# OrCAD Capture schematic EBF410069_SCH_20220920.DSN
size A4; title: 野火_瑞萨启明6M5开发板原理图; rev: V0.1; note: RA6M5 MCU - Power; note: https://yehuosm.tmall.com
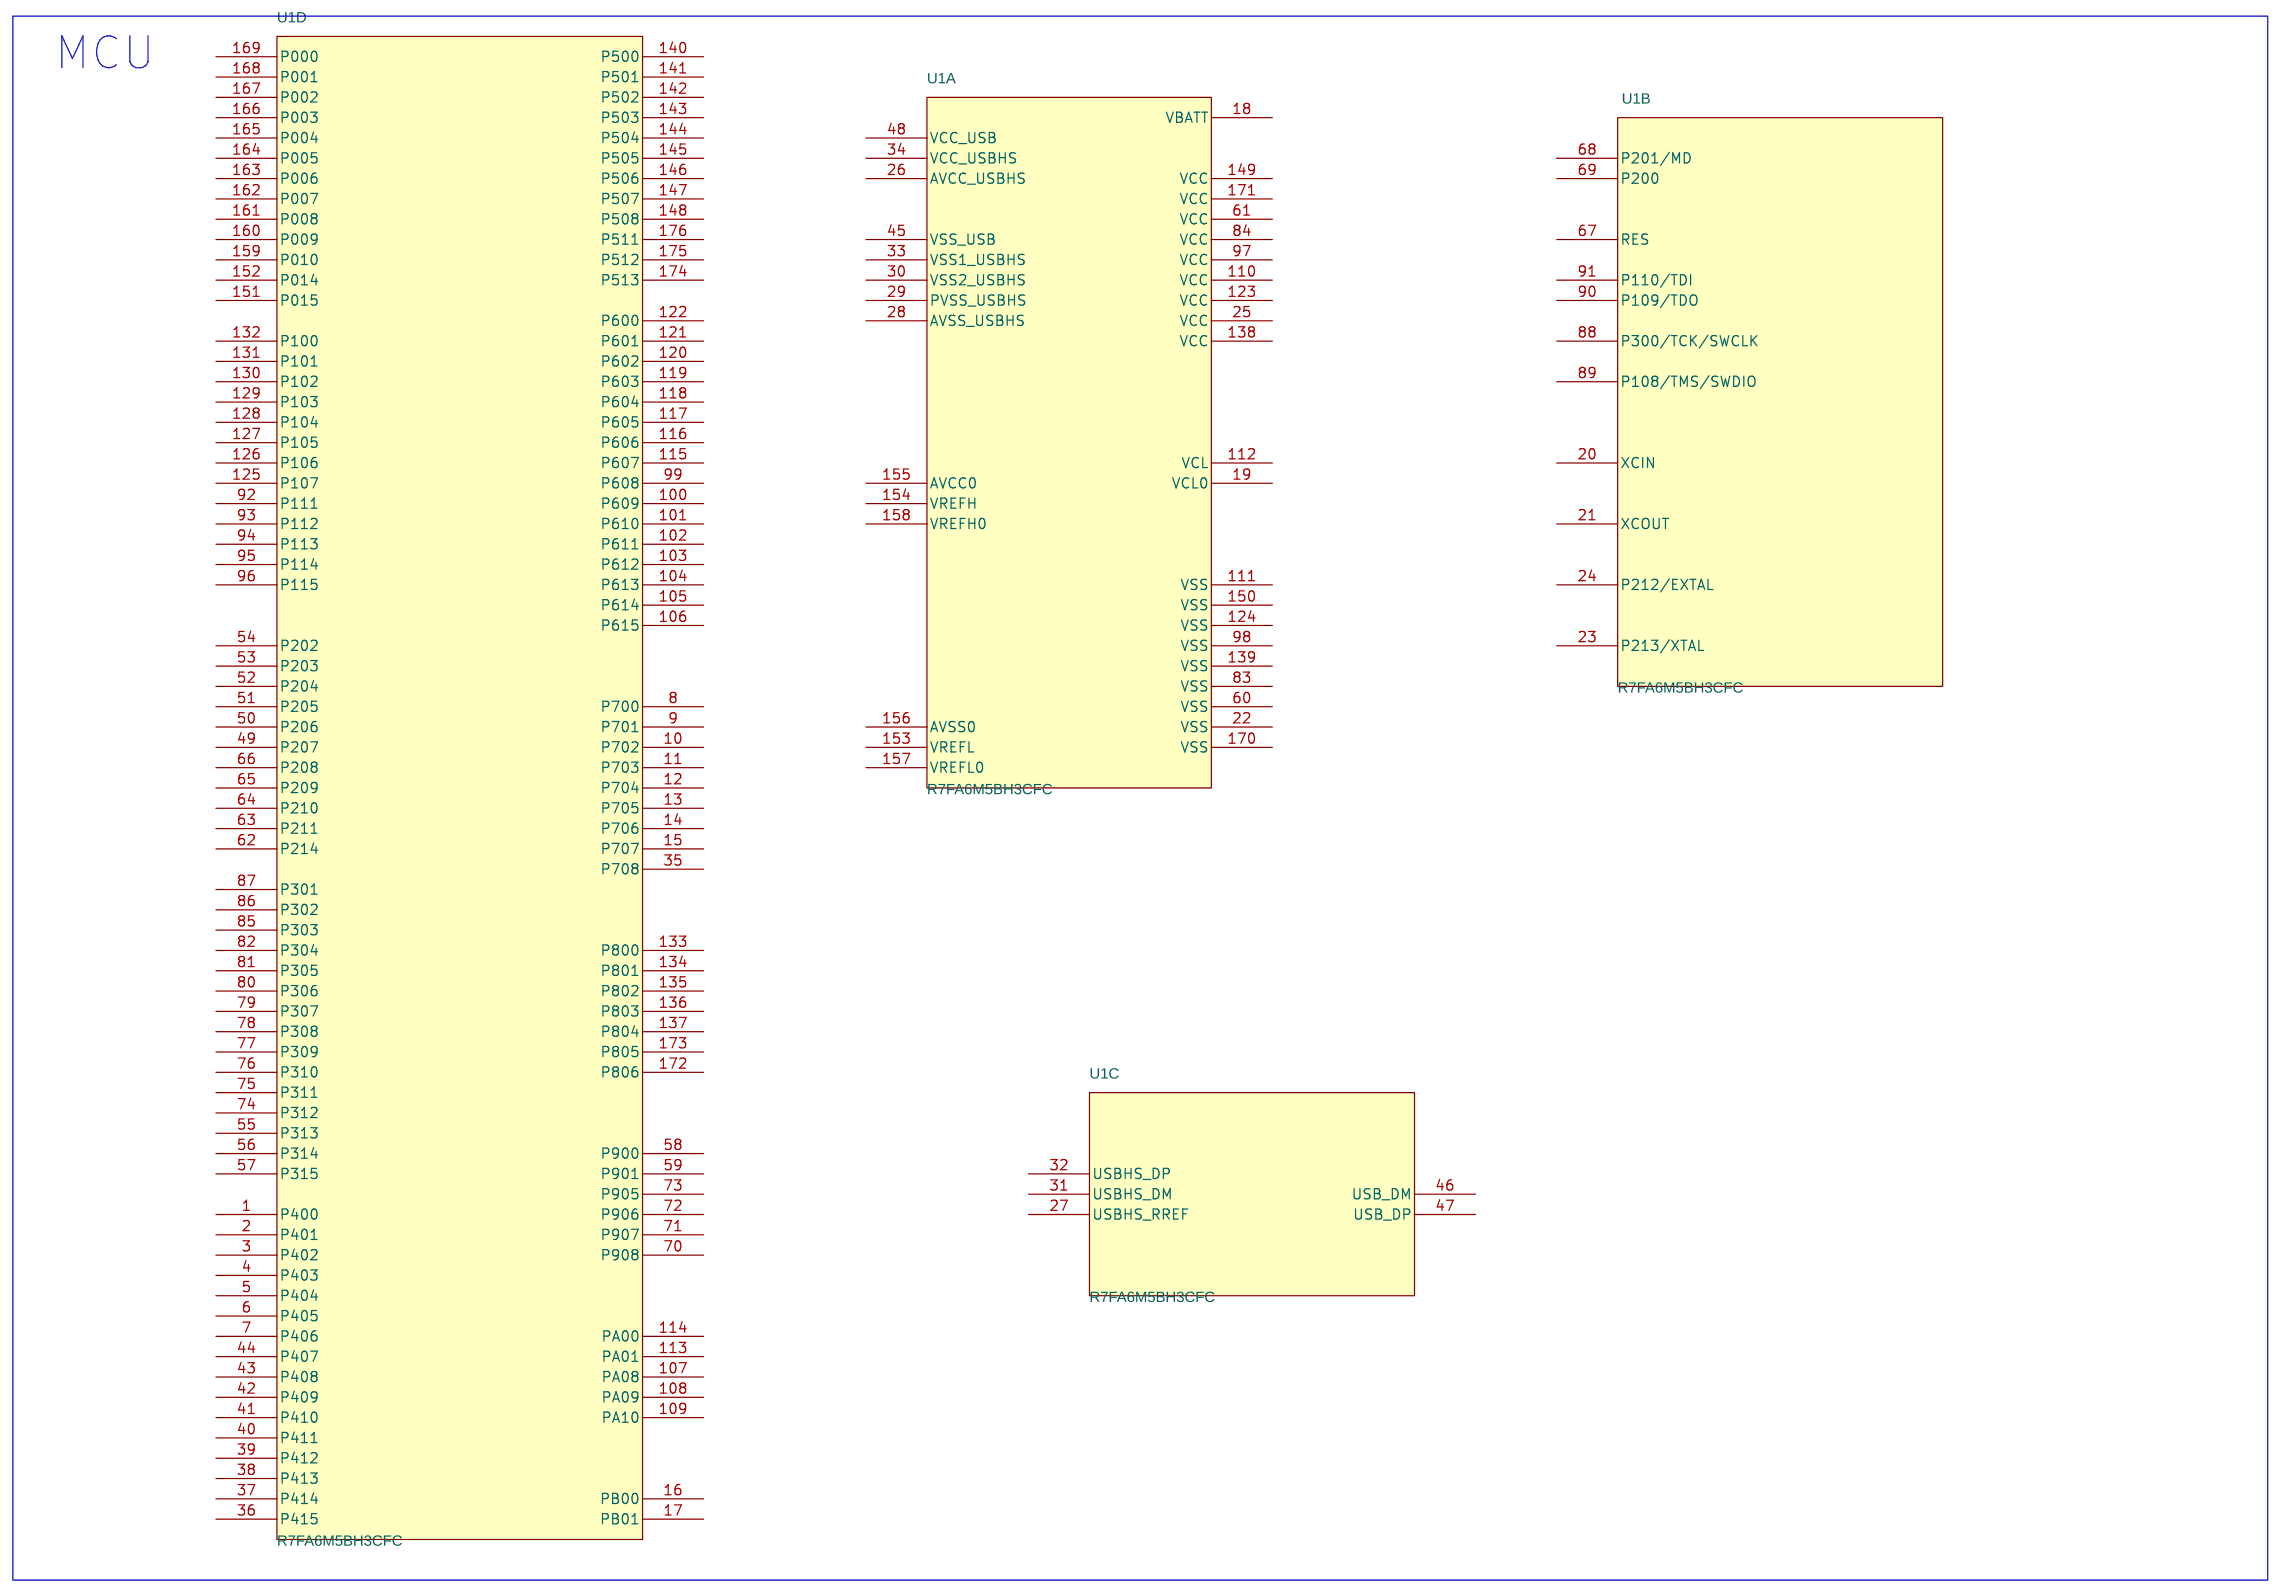
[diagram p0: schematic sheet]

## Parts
U1  R7FA6M5BH3CFC  [P-LFQFP176-24x24-0r50]  (sections A,B,C,D)

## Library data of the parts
U1 = R7FA6M5BH3CFC: 规格: 工作电压 2.7V~3.6V ROM 2M RAM 512K 主频 200MHz; 规格书: 瑞萨RA6M5系列引脚定义_电气特性与封装特性.pdf; 类别: 微控制器-ARM; 品牌: 瑞萨; 生命周期: 量产; 条码: EBF29120558

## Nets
AVCC_USBHS: U1.26(AVCC_USBHS)
AVSS_USBHS: U1.28(AVSS_USBHS)
PVSS_USBHS: U1.29(PVSS_USBHS)
VCC: U1.25(VCC) U1.61(VCC) U1.84(VCC) U1.97(VCC) U1.110(VCC) U1.123(VCC) U1.138(VCC) U1.149(VCC) U1.171(VCC)
VCC_USB: U1.48(VCC_USB)
VCC_USBHS: U1.34(VCC_USBHS)
VSS: U1.22(VSS) U1.60(VSS) U1.83(VSS) U1.98(VSS) U1.111(VSS) U1.124(VSS) U1.139(VSS) U1.150(VSS) U1.170(VSS)
VSS1_USBHS: U1.33(VSS1_USBHS)
VSS2_USBHS: U1.30(VSS2_USBHS)
VSS_USB: U1.45(VSS_USB)

Not connected (* = marked no-connect by the designer): U1 1(P400) 2(P401) 3(P402) 4(P403) 5(P404) 6(P405) 7(P406) 8(P700) 9(P701) 10(P702) 11(P703) 12(P704) 13(P705) 14(P706) 15(P707) 16(PB00) 17(PB01) 18(VBATT) 19(VCL0) 20(XCIN) 21(XCOUT) 23(P213/XTAL) 24(P212/EXTAL) 27(USBHS_RREF) 31(USBHS_DM) 32(USBHS_DP) 35(P708) 36(P415) 37(P414) 38(P413) 39(P412) 40(P411) 41(P410) 42(P409) 43(P408) 44(P407) 46(USB_DM) 47(USB_DP) 49(P207) 50(P206) 51(P205) 52(P204) 53(P203) 54(P202) 55(P313) 56(P314) 57(P315) 58(P900) 59(P901) 62(P214) 63(P211) 64(P210) 65(P209) 66(P208) 67(RES) 68(P201/MD) 69(P200) 70(P908) 71(P907) 72(P906) 73(P905) 74(P312) 75(P311) 76(P310) 77(P309) 78(P308) 79(P307) 80(P306) 81(P305) 82(P304) 85(P303) 86(P302) 87(P301) 88(P300/TCK/SWCLK) 89(P108/TMS/SWDIO) 90(P109/TDO) 91(P110/TDI) 92(P111) 93(P112) 94(P113) 95(P114) 96(P115) 99(P608) 100(P609) 101(P610) 102(P611) 103(P612) 104(P613) 105(P614) 106(P615) 107(PA08) 108(PA09) 109(PA10) 112(VCL) 113(PA01) 114(PA00) 115(P607) 116(P606) 117(P605) 118(P604) 119(P603) 120(P602) 121(P601) 122(P600) 125(P107) 126(P106) 127(P105) 128(P104) 129(P103) 130(P102) 131(P101) 132(P100) 133(P800) 134(P801) 135(P802) 136(P803) 137(P804) 140(P500) 141(P501) 142(P502) 143(P503) 144(P504) 145(P505) 146(P506) 147(P507) 148(P508) 151(P015) 152(P014) 153(VREFL) 154(VREFH) 155(AVCC0) 156(AVSS0) 157(VREFL0) 158(VREFH0) 159(P010) 160(P009) 161(P008) 162(P007) 163(P006) 164(P005) 165(P004) 166(P003) 167(P002) 168(P001) 169(P000) 172(P806) 173(P805) 174(P513) 175(P512) 176(P511)

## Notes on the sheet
- MCU
